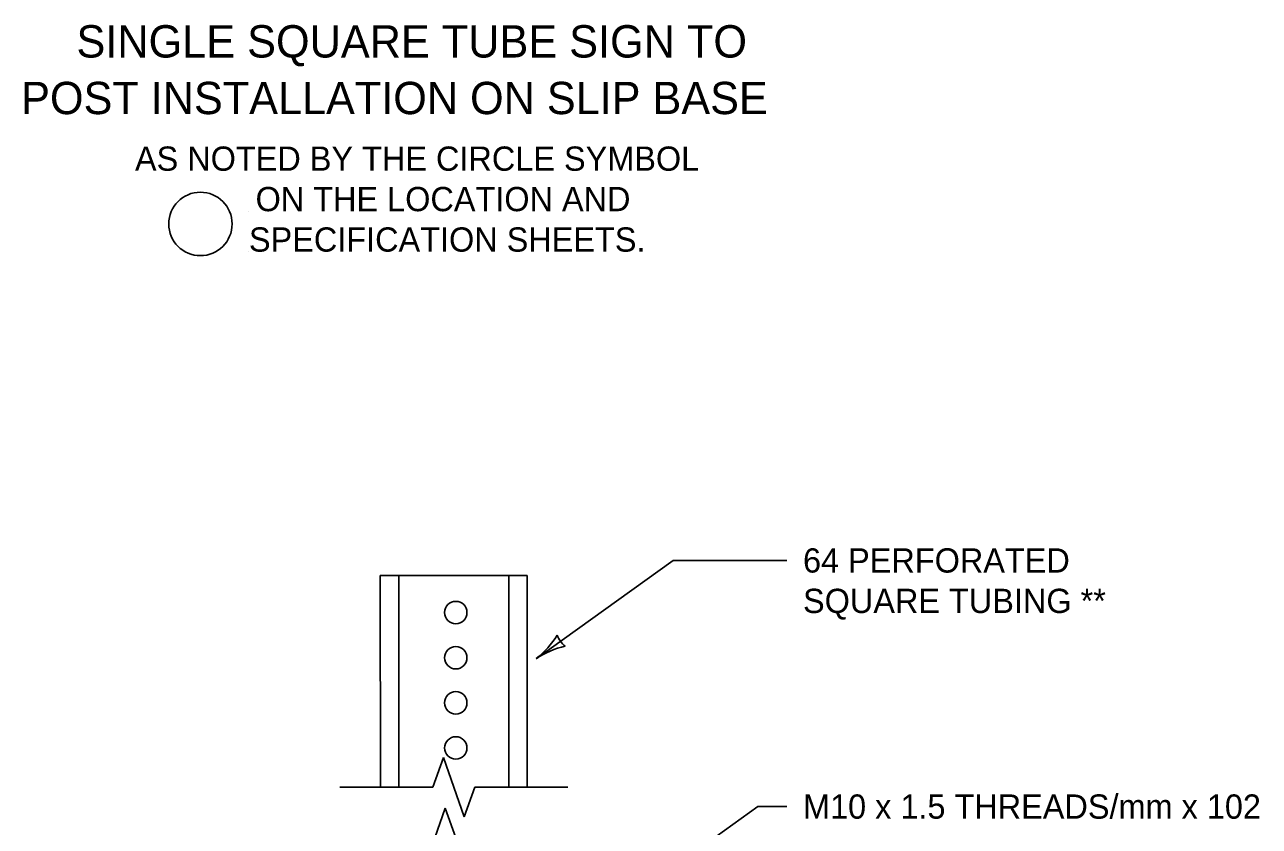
# Model space of a CAD drawing. Extents: x 49940 to 50043, y 49986 to 50011.
# Drawn here: x 50032.561 to 50035.615, y 49994.516 to 49996.498 of the extents above; entities that cross this region are included whole.
import ezdxf

# ---------------------------------------------------------------- set-up
doc = ezdxf.new("R2010")
doc.units = 0
for name, color, linetype in [('Level 1', 7, 'Continuous'), ('Level 2', 7, 'Continuous'), ('Level 3', 7, 'Continuous'), ('Level 4', 7, 'Continuous'), ('Level 6', 7, 'Continuous')]:
    doc.layers.add(name, color=color, linetype=linetype)

msp = doc.modelspace()

# ---------------------------------------------------------------- linework, layer by layer
at = {"layer": 'Level 1'}
msp.add_line((50033.4407, 49995.136), (50033.8043, 49995.136), dxfattribs=at)
for points in [[(50033.4407, 49995.136), (50033.4409, 49994.6122)], [(50033.8043, 49994.6123), (50033.8043, 49995.136)]]:
    msp.add_lwpolyline(points, dxfattribs=at)
for centre in [(50033.6274, 49995.0442), (50033.6274, 49995.0442), (50033.6274, 49994.9326), (50033.6274, 49994.9326), (50033.6274, 49994.821), (50033.6274, 49994.7094)]:
    msp.add_circle(centre, 0.0277, dxfattribs=at)
at = {"layer": 'Level 2'}
for p, q in [((50033.676, 49996.4967), (50033.676, 49996.4967)), ((50033.676, 49996.3567), (50033.676, 49996.3567)), ((50033.1146, 49996.035), (50033.1146, 49996.035)), ((50033.1158, 49995.9368), (50033.1158, 49995.9368))]:
    msp.add_line(p, q, dxfattribs=at)
msp.add_circle((50032.9958, 49996.0052), 0.0784, dxfattribs=at)
at = {"layer": 'Level 3'}
for p, q in [((50033.8264, 49994.9301), (50034.1649, 49995.1731)), ((50034.1649, 49995.1731), (50034.4462, 49995.1731)), ((50034.3744, 49994.5645), (50033.9444, 49994.2558)), ((50034.4462, 49994.5645), (50034.3744, 49994.5645))]:
    msp.add_line(p, q, dxfattribs=at)
for centre, radius, start, end in [((50033.6813, 49995.1128), 0.233, 308.5009, 327.7507), ((50033.9306, 49995.0052), 0.0548, 197.8124, 233.5347), ((50033.9485, 49994.7447), 0.2223, 103.1296, 123.3131)]:
    msp.add_arc(centre, radius, start, end, dxfattribs=at)
at = {"layer": 'Level 4'}
for points in [[(50033.4862, 49995.136), (50033.4863, 49994.6122)], [(50033.7589, 49994.6123), (50033.7589, 49995.136)]]:
    msp.add_lwpolyline(points, dxfattribs=at)
at = {"layer": 'Level 6'}
for p, q in [((50033.5967, 49994.6854), (50033.5708, 49994.6123)), ((50033.5967, 49994.6854), (50033.6226, 49994.6123)), ((50033.341, 49994.6122), (50033.5708, 49994.6122)), ((50033.6226, 49994.6123), (50033.6485, 49994.5392)), ((50033.6744, 49994.6123), (50033.6485, 49994.5392)), ((50033.6744, 49994.6123), (50033.9042, 49994.6123)), ((50033.6015, 49994.5606), (50033.5756, 49994.4875)), ((50033.6015, 49994.5606), (50033.6274, 49994.4875))]:
    msp.add_line(p, q, dxfattribs=at)

# ---------------------------------------------------------------- texts
at = {"layer": 'Level 2'}
for s, height, p in [('SINGLE SQUARE TUBE SIGN TO', 0.08, (50032.6892, 49996.4167)), ('POST INSTALLATION ON SLIP BASE', 0.0799, (50032.5524, 49996.2767)), ('AS NOTED BY THE CIRCLE SYMBOL', 0.06, (50032.8339, 49996.1367)), ('ON THE LOCATION AND', 0.06, (50033.1322, 49996.0367)), ('SPECIFICATION SHEETS.', 0.06, (50033.1158, 49995.9367)), ('64 PERFORATED', 0.06, (50034.4862, 49995.1431)), ('SQUARE TUBING **', 0.06, (50034.4862, 49995.0431)), ('M10 x 1.5 THREADS/mm x 102', 0.06, (50034.4862, 49994.5345))]:
    msp.add_text(s, height=height, dxfattribs=at).set_placement(p)

doc.saveas('drawing.dxf')
